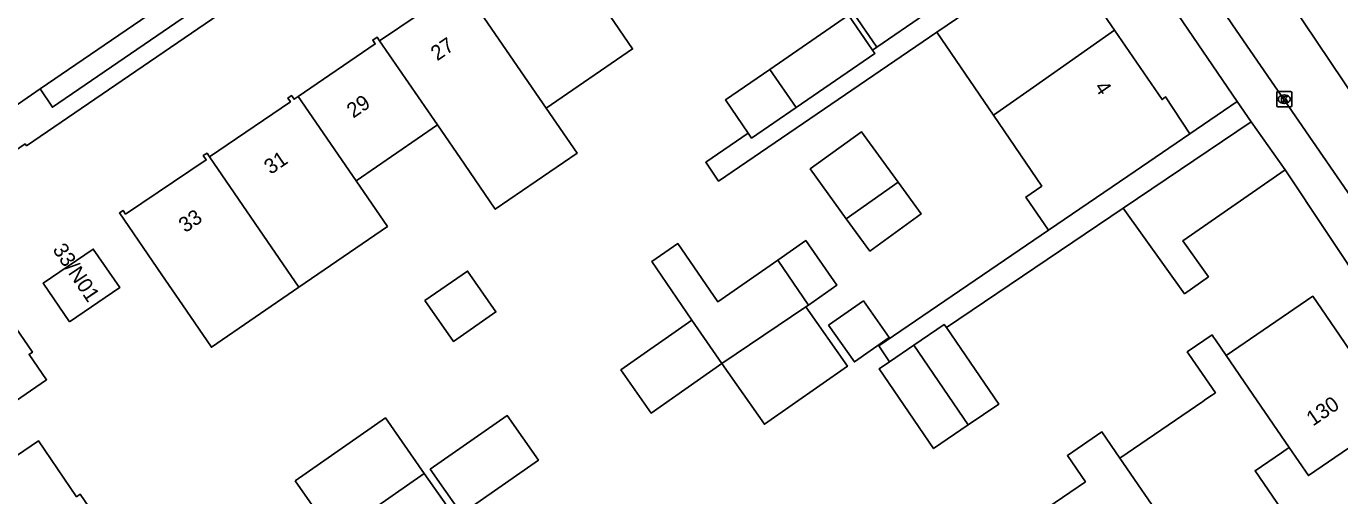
# Model space of a CAD drawing. Extents: x 157466 to 158888, y 383063 to 384677.
# Drawn here: x 158069.4 to 158156.7, y 383369.8 to 383401 of the extents above; entities that cross this region are included whole.
import ezdxf

# ---------------------------------------------------------------- set-up
doc = ezdxf.new("R2010")
doc.units = 0
for name, color, linetype in [('IMGEO_Kolk', 7, 'Continuous'), ('IMGEO_Pand', 7, 'Continuous'), ('IMGEO_Pand_nummerreeks', 7, 'Continuous'), ('IMGEO_Pand_vergunning_verleend', 7, 'Continuous'), ('IMGEO_Rijbaan_lokaal_open', 7, 'Continuous'), ('IMGEO_Voetpad_open', 7, 'Continuous')]:
    doc.layers.add(name, color=color, linetype=linetype)

msp = doc.modelspace()

# ---------------------------------------------------------------- linework, layer by layer
at = {"layer": 'IMGEO_Kolk'}
for p, q in [((158152.552, 383395.767), (158152.552, 383396.619)), ((158152.627, 383396.693), (158153.479, 383396.693)), ((158153.04, 383396.473), (158153.065, 383396.473)), ((158153.553, 383396.619), (158153.553, 383395.767)), ((158153.479, 383395.693), (158152.627, 383395.693)), ((158153.063, 383395.913), (158153.038, 383395.913))]:
    msp.add_line(p, q, dxfattribs=at)
for points in [[(158152.552, 383395.767), (158152.552, 383396.619)], [(158152.627, 383396.693), (158153.479, 383396.693)], [(158152.873, 383396.393), (158152.996, 383396.393), (158152.996, 383396.242), (158153.126, 383396.393), (158153.29, 383396.393), (158153.144, 383396.242), (158153.297, 383395.993), (158153.145, 383395.993), (158153.06, 383396.157), (158152.996, 383396.09), (158152.996, 383395.993), (158152.873, 383395.993), (158152.873, 383396.393)], [(158153.553, 383396.619), (158153.553, 383395.767)], [(158153.479, 383395.693), (158152.627, 383395.693)]]:
    msp.add_lwpolyline(points, dxfattribs=at)
for centre, start, end in [((158152.629, 383396.617), 91.55205, 178.44795), ((158152.629, 383396.617), 91.55205, 178.44795), ((158153.477, 383396.617), 1.55205, 88.44795), ((158153.477, 383396.617), 1.55205, 88.44795), ((158152.629, 383395.769), 181.55205, 268.44795), ((158152.629, 383395.769), 181.55205, 268.44795), ((158153.477, 383395.769), 271.55205, 358.44795), ((158153.477, 383395.769), 271.55205, 358.44795)]:
    msp.add_arc(centre, 0.0765, start, end, dxfattribs=at)
for centre, major_axis, ratio, start_param, end_param in [((158153.039, 383396.193), (-0.387, 0.002), 0.722429, 4.712389, 7.853982), ((158153.064, 383396.193), (-0.39, 0.002), 0.717154, 1.570796, 4.712389)]:
    msp.add_ellipse(centre, major_axis=major_axis, ratio=ratio, start_param=start_param, end_param=end_param, dxfattribs=at)
at = {"layer": 'IMGEO_Pand'}
for points in [[(158129.45, 383406.401), (158123.925, 383402.615), (158125.959, 383399.647)], [(158129.955, 383400.641), (158132.635, 383402.469), (158134.193, 383403.532), (158138.323, 383406.349)], [(158138.323, 383406.349), (158138.492, 383406.101), (158138.244, 383405.931), (158141.769, 383400.782)], [(158098.172, 383404.072), (158097.973, 383403.936), (158098.164, 383403.653), (158092.908, 383400.073)], [(158103.988, 383395.602), (158098.172, 383404.072)], [(158131.489, 383403.435), (158129.143, 383401.828), (158125.959, 383399.647)], [(158103.988, 383395.602), (158109.725, 383399.542), (158107.94, 383402.141)], [(158125.684, 383399.459), (158124.091, 383401.776), (158118.849, 383398.173)], [(158129.955, 383400.641), (158133.719, 383395.122)], [(158141.769, 383400.782), (158136.373, 383396.988), (158133.719, 383395.122)], [(158141.769, 383400.782), (158144.929, 383396.166), (158145.157, 383396.35), (158146.786, 383393.895)], [(158092.908, 383400.073), (158092.74, 383400.321), (158092.449, 383400.123), (158092.617, 383399.875), (158087.491, 383396.372)], [(158096.751, 383394.476), (158092.908, 383400.073)], [(158120.593, 383395.632), (158125.837, 383399.237), (158125.684, 383399.459)], [(158118.849, 383398.173), (158115.892, 383396.14), (158117.417, 383393.922)], [(158120.593, 383395.632), (158118.849, 383398.173)], [(158081.599, 383392.347), (158086.973, 383396.018), (158086.804, 383396.266), (158087.051, 383396.435), (158087.22, 383396.187), (158087.491, 383396.372)], [(158087.491, 383396.372), (158091.339, 383390.768)], [(158096.751, 383394.476), (158098.545, 383391.864), (158100.598, 383388.874), (158106.041, 383392.612), (158103.988, 383395.602)], [(158117.417, 383393.922), (158117.638, 383393.6), (158120.593, 383395.632)], [(158091.339, 383390.768), (158096.751, 383394.476)], [(158133.719, 383395.122), (158136.936, 383390.407), (158135.876, 383389.684), (158137.38, 383387.478)], [(158142.353, 383388.947), (158150.857, 383394.692)], [(158150.857, 383394.692), (158153.12, 383391.491)], [(158127.381, 383390.665), (158124.943, 383394.023), (158121.534, 383391.549), (158123.934, 383388.242)], [(158146.786, 383393.895), (158142.656, 383391.078), (158137.38, 383387.478)], [(158087.535, 383383.678), (158081.726, 383379.69), (158079.792, 383382.512), (158078.429, 383384.501), (158075.604, 383388.625), (158075.852, 383388.792), (158076.019, 383388.543), (158081.374, 383392.151), (158081.177, 383392.444), (158081.43, 383392.594), (158081.599, 383392.347)], [(158081.599, 383392.347), (158085.441, 383386.728), (158087.535, 383383.678)], [(158142.353, 383388.947), (158146.432, 383383.245), (158148.012, 383384.375), (158146.302, 383386.767), (158153.12, 383391.491)], [(158091.339, 383390.768), (158093.429, 383387.725), (158087.535, 383383.678)], [(158123.934, 383388.242), (158127.381, 383390.665)], [(158127.381, 383390.665), (158128.91, 383388.558), (158125.501, 383386.084), (158123.934, 383388.242)], [(158119.376, 383385.487), (158115.396, 383382.701), (158112.732, 383386.581), (158111.001, 383385.392), (158113.675, 383381.496)], [(158121.428, 383382.499), (158123.314, 383383.819), (158121.236, 383386.788), (158119.376, 383385.487)], [(158072.286, 383381.388), (158075.627, 383383.66), (158073.869, 383386.222), (158070.537, 383383.959), (158072.286, 383381.388)], [(158121.428, 383382.499), (158119.376, 383385.487)], [(158095.922, 383382.798), (158097.814, 383380.071), (158100.643, 383382.034), (158098.751, 383384.761), (158095.922, 383382.798)], [(158060.325, 383372.853), (158057.531, 383376.932), (158067.02, 383383.433), (158069.814, 383379.354), (158069.602, 383379.209), (158070.758, 383377.521), (158065.909, 383374.199), (158064.753, 383375.887), (158060.325, 383372.853)], [(158153.38, 383373.018), (158154.663, 383371.146), (158160.417, 383375.087), (158156.722, 383380.483), (158154.946, 383383.077), (158152.084, 383381.116), (158149.191, 383379.133)], [(158115.665, 383378.597), (158121.245, 383382.367)], [(158115.665, 383378.597), (158118.49, 383374.561), (158124.006, 383378.422), (158121.245, 383382.367)], [(158121.245, 383382.367), (158121.428, 383382.499)], [(158122.76, 383381.154), (158124.47, 383378.71), (158126.782, 383380.328), (158125.072, 383382.772), (158122.76, 383381.154)], [(158113.675, 383381.496), (158108.945, 383378.185), (158110.961, 383375.304), (158115.665, 383378.597)], [(158113.675, 383381.496), (158115.665, 383378.597)], [(158130.587, 383380.998), (158130.442, 383381.211), (158128.416, 383379.825)], [(158132.047, 383374.527), (158134.069, 383375.91), (158130.587, 383380.998)], [(158142.128, 383372.31), (158147.647, 383376.087), (158147.848, 383376.225), (158148.283, 383376.523), (158148.477, 383376.656), (158146.707, 383379.239), (158146.61, 383379.381), (158148.251, 383380.506), (158148.348, 383380.363), (158148.474, 383380.179), (158149.191, 383379.133)], [(158128.416, 383379.825), (158126.812, 383378.727)], [(158128.416, 383379.825), (158132.047, 383374.527)], [(158126.812, 383378.727), (158126.114, 383378.25), (158129.741, 383372.949), (158132.047, 383374.527)], [(158149.191, 383379.133), (158150.967, 383376.541), (158153.38, 383373.018)], [(158098.346, 383368.602), (158096.273, 383371.568), (158101.387, 383375.142), (158103.459, 383372.177), (158098.346, 383368.602)], [(158063.457, 383349.42), (158070.453, 383354.196), (158070.741, 383353.776), (158073.267, 383355.504), (158072.98, 383355.926), (158079.5, 383360.371), (158073, 383369.907), (158072.752, 383369.739), (158070.217, 383373.469), (158065.818, 383370.478), (158066.004, 383370.206), (158059.232, 383365.6), (158059.047, 383365.873), (158054.649, 383362.864), (158057.202, 383359.135), (158056.946, 383358.96), (158063.457, 383349.42)], [(158136.301, 383368.322), (158139.833, 383370.74), (158138.637, 383372.484), (158140.931, 383374.057), (158142.128, 383372.31)], [(158153.38, 383373.018), (158153.193, 383372.89), (158152.867, 383372.667), (158151.113, 383371.466), (158153.994, 383367.258), (158148.276, 383363.342)], [(158148.276, 383363.342), (158142.128, 383372.31)], [(158091.622, 383368.318), (158093.517, 383365.607), (158097.773, 383368.581), (158095.878, 383371.292), (158091.622, 383368.318)]]:
    msp.add_lwpolyline(points, dxfattribs=at)
at = {"layer": 'IMGEO_Pand_vergunning_verleend'}
msp.add_lwpolyline([(158087.291, 383370.796), (158093.292, 383374.991), (158095.878, 383371.292), (158097.773, 383368.581), (158093.517, 383365.607), (158091.771, 383364.387), (158087.291, 383370.796)], dxfattribs=at)
at = {"layer": 'IMGEO_Rijbaan_lokaal_open'}
for points in [[(158070.336, 383396.873), (158084.142, 383406.331)], [(158158.734, 383394.78), (158153.46, 383402.634)], [(158158.182, 383388.686), (158149.868, 383400.793), (158148.913, 383402.192)], [(158070.336, 383396.873), (158067.203, 383394.733)]]:
    msp.add_lwpolyline(points, dxfattribs=at)
at = {"layer": 'IMGEO_Voetpad_open'}
for points in [[(158043.948, 383373.738), (158044.138, 383374.89), (158044.309, 383375.924), (158047.833, 383378.409), (158069.337, 383393.213), (158069.427, 383393.097), (158110.929, 383421.479), (158124.53, 383430.909)], [(158108.868, 383423.27), (158109.692, 383422.05), (158071.149, 383395.654), (158070.336, 383396.873)], [(158141.448, 383408.481), (158149.935, 383396.043)], [(158117.417, 383393.922), (158114.59, 383391.994), (158115.444, 383390.743), (158129.955, 383400.641)], [(158125.959, 383399.647), (158125.684, 383399.459)], [(158146.786, 383393.895), (158149.935, 383396.043)], [(158149.935, 383396.043), (158150.857, 383394.692)], [(158153.12, 383391.491), (158158.608, 383383.217), (158165.141, 383373.559), (158165.177, 383373.504), (158165.304, 383373.283), (158165.411, 383373.052), (158165.497, 383372.812), (158165.561, 383372.566), (158165.602, 383372.315), (158165.622, 383372.061), (158165.618, 383371.807), (158165.592, 383371.553), (158165.543, 383371.304), (158165.472, 383371.059), (158165.379, 383370.822), (158165.266, 383370.594), (158165.133, 383370.377), (158164.98, 383370.173), (158164.811, 383369.983), (158164.625, 383369.809)], [(158130.587, 383380.998), (158142.353, 383388.947)], [(158137.38, 383387.478), (158126.094, 383379.777), (158126.812, 383378.727)]]:
    msp.add_lwpolyline(points, dxfattribs=at)

# ---------------------------------------------------------------- texts
at = {"layer": 'IMGEO_Pand_nummerreeks'}
for s, rotation, p in [('27', 34.29725, (158096.736, 383398.704)), ('4', 304.39507, (158140.396, 383396.982)), ('29', 34.29725, (158091.15, 383394.893)), ('31', 34.29954, (158085.657, 383391.147)), ('33', 34.29725, (158079.978, 383387.273)), ('33/N01', 303.80796, (158071.128, 383386.187)), ('130', 34.40612, (158154.964, 383374.406))]:
    msp.add_text(s, height=1, rotation=rotation, dxfattribs=at).set_placement(p)

doc.saveas('drawing.dxf')
